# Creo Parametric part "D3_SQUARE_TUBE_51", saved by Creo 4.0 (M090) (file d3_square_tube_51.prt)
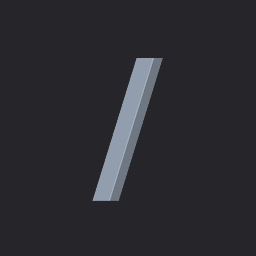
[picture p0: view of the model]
Units: Custom; MM, KILOGRAM, SECS
Materials in the file: STEEL

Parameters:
  BUW_NAME = "SQUARE TUBE"
  BUW_TYPE = "DIN EN 10210"
  BUW_SIZE = "60x60x3.0"
  BUW_LENGTH_STR = "611.5"
  PTC_MATERIAL_NAME = "STEEL"
  BUW_PROFIL_TYPE = "square_tube"
  BUW_PROFILE_PATH = "parts/profiles/steel_beams_mm/"
  BUW_PROFILE_NAME_LANG = "SQUARE TUBE"
  BUW_TAB_SEL_INFO = "2  0 2  3 19"
  MITRE_SYM_X_S = "\"
  MITRE_SYM_X_E = "\"
  MITRE_SYM_X = "\---\"
  MITRE_BOM_X = "X \---\"
  MITRE_SYM_Y_S = "|"
  MITRE_SYM_Y_E = "|"
  MITRE_SYM_Y = "|---|"
  BUW_DOUBLE_TO_STR_INFO = "X_ROT_S2 2 X_ROT_E2 2 Y_ROT_S2 2 Y_ROT_E2 2"
  X_ROT_S2_STR = "51.34"
  X_ROT_E2_STR = "51.34"
  Y_ROT_S2_STR = "90"
  Y_ROT_E2_STR = "90"
  BOM_ANGLE_S = "X 51.34°"
  BOM_ANGLE_E = "X 51.34°"
  EFX_ITEM_NR = "4"
  PROFIL_RASTER_POS = "X_0"
  BUW_OBJECT_ROLE = "PROFIL_SYSTEM_BORE_END_POINTS"
  PRO_UNIT_SYS = "Custom"

Other parameters: BUW_LENGTH, X_ROT_S2, X_ROT_E2, Y_ROT_S2, Y_ROT_E2, D8, D93, D94, d26, d8, d93, d94, d98, D98, D0, D4, D1, D5, SHEAR_MODULUS, THERM_EXPANSION_REF_TEMPERATURE, STRUCTURAL_DAMPING_COEFFICIENT, STRESS_LIMIT_FOR_TENSION, STRESS_LIMIT_FOR_COMPRESSION, STRESS_LIMIT_FOR_SHEAR, EMISSIVITY

Created from: SQUARE_TUBE.PRT

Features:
  1. datum plane "YZ"
  2. datum plane "XZ"
  3. datum plane "XY"
  4. coordinate system
  5. coordinate system
  6. coordinate system
  7. coordinate system
  8. datum plane "DTM3"
  9. datum plane "DTM4"
  10. datum plane "DTM5"
  11. protrusion
  12. round
  13. round
  14. datum axis
  15. datum point "PNT0"
  16. datum point

Other named items: PROFIL_CUT_QUILT, PROFILE_LENGTH_DIM, CONTACT_SURF_3, CONTACT_SURF_2, CONTACT_SURF_1, CONTACT_SURF_0, E, START_SURFACE, END_SURFACE, SIDE_SURF_3, SIDE_SURF_0, SIDE_SURF_1, SIDE_SURF_2, EDGE_7_S, EDGE_7_E, EDGE_1_S, EDGE_1_E, EDGE_3_S, EDGE_3_E, EDGE_5_S, EDGE_5_E, EDGE_6_S, EDGE_4_S, EDGE_2_S, EDGE_0_S, EDGE_6_E, EDGE_4_E, EDGE_2_E, EDGE_0_E, CS0, CS_S, CS_E, CS3

Named dimensions: X_ROT_S, Y_ROT_S, Z_OFF_S, X_ROT_E, Y_ROT_E, Z_OFF_E, PC_L, BUW_LENGTH_Z_MIN, BUW_LENGTH_DIM

Layers: 00_PROFIL_DATUM, 00_PROFIL_DRW_HIDE, 00_PROFIL_END_CSYS, 00_PROFIL_GEOMETRY, 00_PROFIL_QUILT, 00_PROFIL_SIZE_NOTE

Surfaces: 10 plane, 8 cylinder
